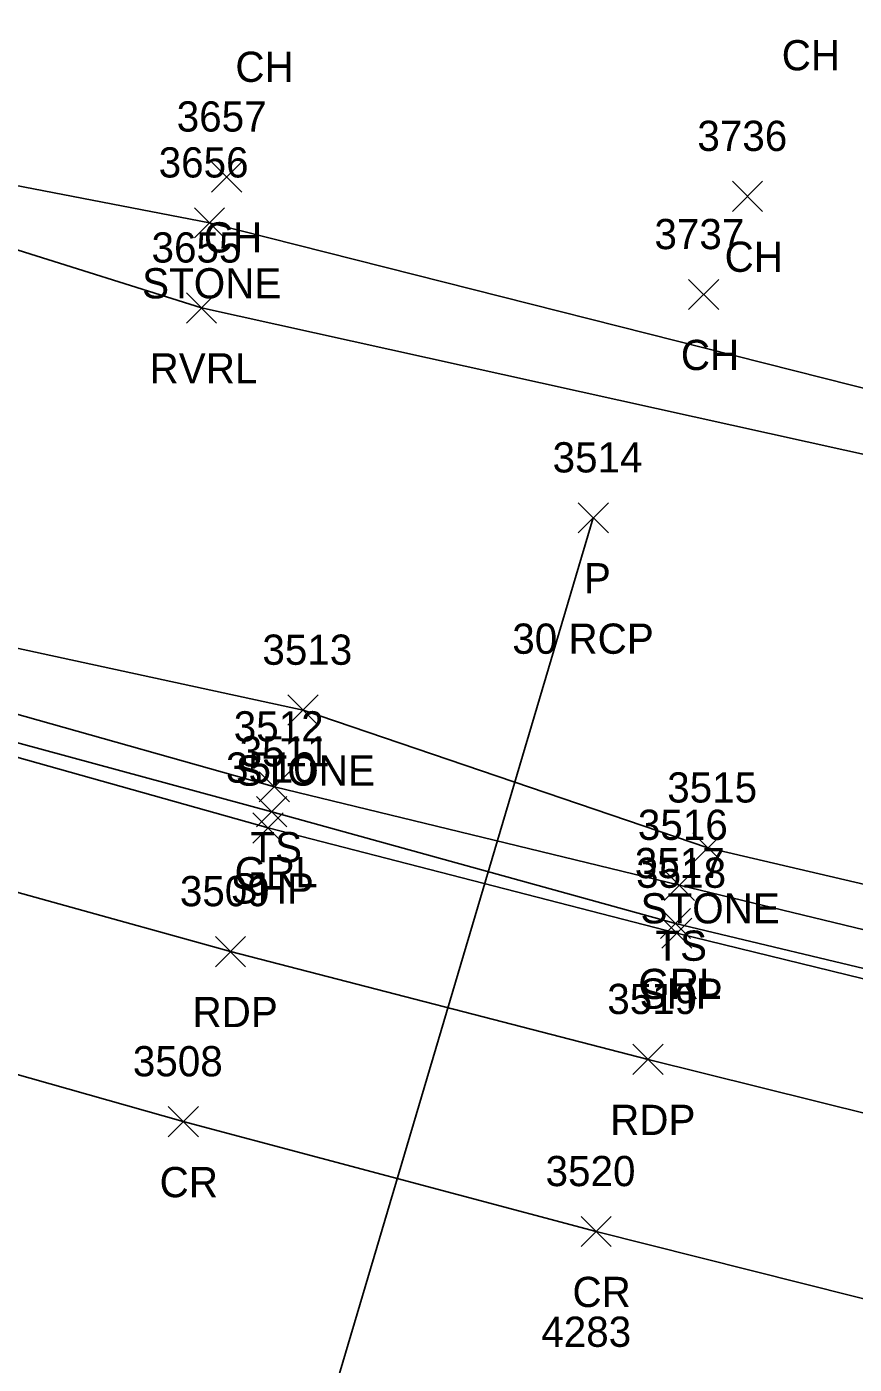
# Model space of a CAD drawing. Extents: x 1647574 to 1652703, y 212895 to 228670.
# Drawn here: x 1648753.8 to 1648808.6, y 227168.5 to 227257.1 of the extents above; entities that cross this region are included whole.
import ezdxf

# ---------------------------------------------------------------- set-up
doc = ezdxf.new("R2010")
doc.units = 0
for name, color, linetype in [('D_A', 7, 'Continuous'), ('D_C', 7, 'Continuous'), ('D_I', 7, 'Continuous'), ('D_TIC', 7, 'Continuous'), ('DCP', 7, 'Continuous'), ('L_A', 7, 'Continuous'), ('L_I', 7, 'Continuous'), ('L_TIC', 7, 'Continuous'), ('LASF', 7, 'Continuous'), ('LAWE', 7, 'Continuous'), ('LELB', 7, 'Continuous'), ('P_A', 7, 'Continuous'), ('P_I', 7, 'Continuous'), ('P_TIC', 7, 'Continuous'), ('PET', 7, 'Continuous'), ('PRC', 7, 'Continuous'), ('PSP', 7, 'Continuous'), ('R_A', 7, 'Continuous'), ('R_I', 7, 'Continuous'), ('R_TIC', 7, 'Continuous'), ('RGR', 7, 'Continuous')]:
    doc.layers.add(name, color=color, linetype=linetype)

msp = doc.modelspace()

# ---------------------------------------------------------------- linework, layer by layer
at = {"layer": 'D_TIC'}
for points in [[(1648790.297, 227223.558), (1648792.297, 227225.558)], [(1648792.297, 227223.558), (1648790.297, 227225.558)]]:
    msp.add_lwpolyline(points, dxfattribs=at)
at = {"layer": 'DCP'}
msp.add_lwpolyline([(1648791.297, 227224.558), (1648764.655, 227134.747)], dxfattribs=at)
at = {"layer": 'L_TIC'}
for points in [[(1648766.033, 227246.117), (1648768.033, 227248.117)], [(1648768.033, 227246.117), (1648766.033, 227248.117)], [(1648800.499, 227244.834), (1648802.499, 227246.834)], [(1648802.499, 227244.834), (1648800.499, 227246.834)], [(1648764.894, 227243.077), (1648766.894, 227245.077)], [(1648766.894, 227243.077), (1648764.894, 227245.077)], [(1648797.602, 227238.335), (1648799.602, 227240.335)], [(1648799.602, 227238.335), (1648797.602, 227240.335)], [(1648764.368, 227237.448), (1648766.368, 227239.448)], [(1648766.368, 227237.448), (1648764.368, 227239.448)], [(1648771.089, 227210.83), (1648773.089, 227212.83)], [(1648773.089, 227210.83), (1648771.089, 227212.83)], [(1648769.192, 227205.754), (1648771.192, 227207.754)], [(1648771.192, 227205.754), (1648769.192, 227207.754)], [(1648797.883, 227201.714), (1648799.883, 227203.714)], [(1648799.883, 227201.714), (1648797.883, 227203.714)], [(1648795.996, 227199.241), (1648797.996, 227201.241)], [(1648797.996, 227199.241), (1648795.996, 227201.241)]]:
    msp.add_lwpolyline(points, dxfattribs=at)
at = {"layer": 'LASF'}
for points in [[(1648499.797, 227390.788), (1648534.237, 227361.964), (1648564.139, 227335.998), (1648594.151, 227310.22), (1648628.599, 227293.401), (1648654.269, 227279.63), (1648686.156, 227265.624), (1648717.135, 227256.764), (1648740.627, 227248.949), (1648765.894, 227244.077), (1648814.223, 227231.854), (1648833.279, 227225.74), (1648856.547, 227221.689), (1648882.063, 227215.369), (1648909.355, 227210.97), (1648936.503, 227203.804), (1648961.566, 227198.174), (1648983.303, 227192.864), (1648997.705, 227192.889), (1649002.003, 227200.334)], [(1648591.009, 227270.343), (1648624.693, 227258.455), (1648664.933, 227242.862), (1648702.926, 227233.816), (1648737.154, 227219.4), (1648772.089, 227211.83), (1648798.883, 227202.714), (1648829.377, 227195.595), (1648870.643, 227189.301), (1648888.064, 227189.998), (1648910.238, 227184.26), (1648945.065, 227174.552), (1648988.129, 227167.991), (1649019.013, 227162.278), (1649093.93, 227148.389), (1649131.468, 227140.127), (1649155.823, 227137.226), (1649206.951, 227127.276), (1649258.232, 227116.863), (1649289.141, 227114.771), (1649313.58, 227109.451)]]:
    msp.add_lwpolyline(points, dxfattribs=at)
at = {"layer": 'LAWE'}
msp.add_lwpolyline([(1648476.378, 227405.216), (1648496.153, 227388.221), (1648530.655, 227356.871), (1648567.867, 227325.979), (1648591.316, 227307.766), (1648628.319, 227290.488), (1648653.198, 227277.298), (1648685.977, 227263.737), (1648715.079, 227253.44), (1648739.533, 227246.568), (1648765.368, 227238.448), (1648812.936, 227227.92), (1648833.651, 227223.234), (1648856.007, 227219.814), (1648882.174, 227213.58), (1648908.492, 227208.957)], dxfattribs=at)
at = {"layer": 'LELB'}
msp.add_lwpolyline([(1648597.273, 227264.486), (1648633.73, 227250.634), (1648664.389, 227240.318), (1648701.872, 227228.729), (1648735.461, 227216.545), (1648770.192, 227206.754), (1648796.996, 227200.241), (1648829.006, 227192.504), (1648869.112, 227184.885), (1648887.117, 227184.175), (1648909.076, 227180.513), (1648944.404, 227172.664), (1648985.415, 227160.185), (1649015.972, 227155.751), (1649030.56, 227151.792), (1649075.874, 227142.707), (1649094.964, 227142.334), (1649128.793, 227137.178), (1649163.599, 227126.992), (1649206.12, 227120.023), (1649254.696, 227110.714), (1649288.497, 227104.847), (1649312.044, 227099.384)], dxfattribs=at)
at = {"layer": 'P_TIC'}
for points in [[(1648768.769, 227203.03), (1648770.769, 227205.03)], [(1648770.769, 227203.03), (1648768.769, 227205.03)], [(1648795.828, 227196.07), (1648797.828, 227198.07)], [(1648797.828, 227196.07), (1648795.828, 227198.07)], [(1648766.283, 227194.85), (1648768.283, 227196.85)], [(1648768.283, 227194.85), (1648766.283, 227196.85)], [(1648793.922, 227187.715), (1648795.922, 227189.715)], [(1648795.922, 227187.715), (1648793.922, 227189.715)], [(1648763.162, 227183.595), (1648765.162, 227185.595)], [(1648765.162, 227183.595), (1648763.162, 227185.595)], [(1648790.485, 227176.326), (1648792.485, 227178.326)], [(1648792.485, 227176.326), (1648790.485, 227178.326)]]:
    msp.add_lwpolyline(points, dxfattribs=at)
at = {"layer": 'PET'}
msp.add_lwpolyline([(1648582.821, 227256.084), (1648618.147, 227242.999), (1648661.462, 227228.082), (1648697.31, 227216.445), (1648732, 227205.65), (1648767.283, 227195.85), (1648794.922, 227188.715), (1648824.663, 227181.318), (1648870.225, 227171.495), (1648904.553, 227164.504), (1648941.404, 227157.321), (1648982.588, 227149.559), (1649013.451, 227143.774), (1649051.482, 227136.017), (1649092.559, 227128.28), (1649129.41, 227121.264), (1649164.129, 227114.968), (1649203.067, 227107.319), (1649253.119, 227097.953), (1649285.33, 227091.532), (1649309.805, 227086.858)], dxfattribs=at)
at = {"layer": 'PRC'}
msp.add_lwpolyline([(1648578.474, 227245.088), (1648614.144, 227232.377), (1648658.376, 227217.212), (1648693.17, 227205.447), (1648728.772, 227194.614), (1648764.162, 227184.595), (1648791.485, 227177.326), (1648822.259, 227169.584), (1648868.208, 227159.379), (1648902.01, 227152.53), (1648938.677, 227144.922), (1648979.678, 227137.482), (1649011.638, 227131.497), (1649049.006, 227124.369), (1649090.363, 227116.947), (1649126.936, 227110.347), (1649164.154, 227103.487), (1649199.467, 227096.77), (1649251.628, 227086.358), (1649284.276, 227080.21), (1649307.757, 227075.596)], dxfattribs=at)
at = {"layer": 'PSP'}
msp.add_lwpolyline([(1648480.186, 227300.935), (1648523.095, 227287.235), (1648552.393, 227275.528), (1648583.82, 227263.797), (1648620.778, 227250.204), (1648663.69, 227235.815), (1648700.093, 227224.251), (1648734.52, 227213.948), (1648769.769, 227204.03), (1648796.828, 227197.07), (1648827.571, 227189.553), (1648872.239, 227179.077), (1648906.708, 227172.293), (1648943.109, 227165.503), (1648984.425, 227157.969), (1649015.263, 227151.943), (1649051.882, 227144.802), (1649094.443, 227136.72), (1649131.243, 227129.788), (1649164.299, 227122.927), (1649204.314, 227115.136), (1649254.536, 227105.699), (1649286.332, 227099.339), (1649311.67, 227094.73)], dxfattribs=at)
at = {"layer": 'R_TIC'}
for points in [[(1648769.018, 227204.103), (1648771.018, 227206.103)], [(1648771.018, 227204.103), (1648769.018, 227206.103)], [(1648795.736, 227196.709), (1648797.736, 227198.709)], [(1648797.736, 227196.709), (1648795.736, 227198.709)]]:
    msp.add_lwpolyline(points, dxfattribs=at)
at = {"layer": 'RGR'}
msp.add_lwpolyline([(1648566.499, 227274.336), (1648584.93, 227265.187), (1648621.098, 227251.014), (1648663.82, 227236.679), (1648700.169, 227224.812), (1648734.661, 227214.696), (1648770.018, 227205.103), (1648796.736, 227197.709), (1648827.747, 227190.287), (1648869.576, 227180.639), (1648886.4, 227182.638)], dxfattribs=at)

# ---------------------------------------------------------------- texts
at = {"layer": 'D_A'}
msp.add_text('P', height=2, dxfattribs=at).set_placement((1648790.675, 227219.558))
at = {"layer": 'D_C'}
msp.add_text('30 RCP', height=2, dxfattribs=at).set_placement((1648785.935, 227215.558))
at = {"layer": 'D_I'}
msp.add_text('3514', height=2, dxfattribs=at).set_placement((1648788.604, 227227.558))
at = {"layer": 'L_A'}
for s, p in [('CH', (1648803.768, 227254.17)), ('CH', (1648767.609, 227253.405)), ('CH', (1648765.521, 227242.117)), ('CH', (1648799.987, 227240.834)), ('STONE', (1648761.438, 227239.077)), ('CH', (1648797.09, 227234.335)), ('RVRL', (1648761.935, 227233.448)), ('STONE', (1648767.632, 227206.83)), ('TS', (1648768.602, 227201.754)), ('STONE', (1648794.427, 227197.714)), ('TS', (1648795.405, 227195.241))]:
    msp.add_text(s, height=2, dxfattribs=at).set_placement(p)
at = {"layer": 'L_I'}
for s, p in [('3657', (1648763.726, 227250.117)), ('3736', (1648798.184, 227248.834)), ('3656', (1648762.532, 227247.077)), ('3737', (1648795.342, 227242.335)), ('3655', (1648762.061, 227241.448)), ('3513', (1648769.396, 227214.83)), ('3512', (1648767.5, 227209.754)), ('3515', (1648796.19, 227205.714)), ('3516', (1648794.248, 227203.241))]:
    msp.add_text(s, height=2, dxfattribs=at).set_placement(p)
at = {"layer": 'P_A'}
for s, p in [('SHP', (1648767.304, 227199.03)), ('SHP', (1648794.363, 227192.07)), ('RDP', (1648764.771, 227190.85)), ('RDP', (1648792.41, 227183.715)), ('CR', (1648762.595, 227179.595)), ('CR', (1648789.918, 227172.326))]:
    msp.add_text(s, height=2, dxfattribs=at).set_placement(p)
at = {"layer": 'P_I'}
for s, p in [('3510', (1648766.99, 227207.03)), ('3518', (1648794.135, 227200.07)), ('3509', (1648763.936, 227198.85)), ('3519', (1648792.222, 227191.715)), ('3508', (1648760.824, 227187.595)), ('3520', (1648788.138, 227180.326)), ('4283', (1648787.854, 227169.692))]:
    msp.add_text(s, height=2, dxfattribs=at).set_placement(p)
at = {"layer": 'R_A'}
for p in [(1648767.561, 227200.103), (1648794.279, 227192.709)]:
    msp.add_text('GRL', height=2, dxfattribs=at).set_placement(p)
at = {"layer": 'R_I'}
for s, p in [('3511', (1648767.892, 227208.103)), ('3517', (1648794.043, 227200.709))]:
    msp.add_text(s, height=2, dxfattribs=at).set_placement(p)

doc.saveas('drawing.dxf')
